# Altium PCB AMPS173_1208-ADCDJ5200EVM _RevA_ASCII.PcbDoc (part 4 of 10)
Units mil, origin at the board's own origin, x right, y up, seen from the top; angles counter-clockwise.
Board outline 10500 x 2750 mil, 14 copper layers (Top Copper, Layer 2 (GND1), Layer 3 (SIG1), Layer 4 (GND2, Layer 5 (PWR1), Layer 6 (GND3), Layer 7 (PWR/SIGNAL2), Layer 8 (PWR/SIGNAL3), Layer 9 (GND4), Layer 10 PWR2), Layer 11 (GND5), Layer 12 (SIG4), Layer 13 (GND6), Bottom Copper), stack 60.6 mil thick; 701 components, 826 nets, 3386 pads, 2128 vias.
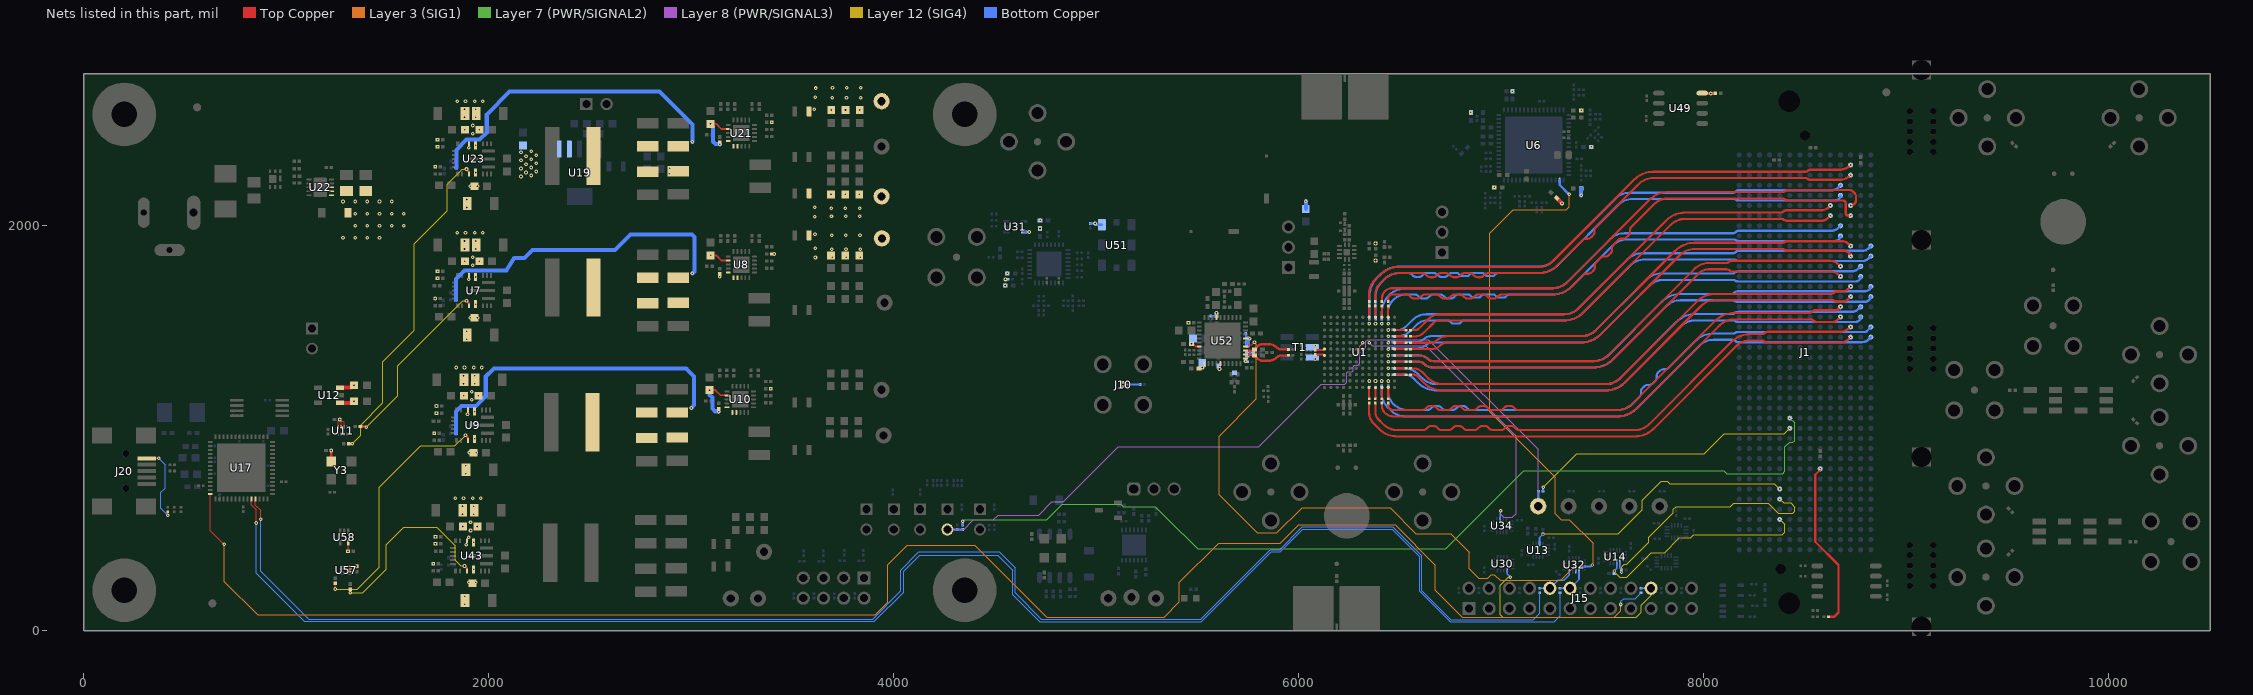
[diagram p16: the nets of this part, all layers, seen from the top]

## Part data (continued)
U17: library part CMP-0081661-1, "Future Technology Devices International Ltd FT4232H Quad High Speed USB to Multipurpose UART/MPSSE IC, VQFN-56", Manufacturer=FTDI, Supplier Part Number 1=768-1277-ND
U18: library part CMP-0081524-1, "1K Microwire Compatible Serial EEPROM, TSSOP-8", Manufacturer=Microchip, Supplier Part Number 1=93LC46B-I/ST-ND
U19: library part CMP-0036724-1, "Single Output Fast Transient Response LDO, 1.5 A,Adjustable Output, 2.1 to 20 V Input, 6-pin SOT-223 (DCQ), -40 to 125 degC, Green (RoHS & no Sb/Br)", Manufacturer="Texas Instruments"
U20: library part CMP-0005258-2, "64K I2C Smart Serial EEPROM, SOIC-8", Manufacturer=Microchip, Supplier Part Number 1=24LC65-I/SM-ND
U22: library part CMP-0074225-5, "12V, 5A, 30mO eFuse with Adjustable +/-15% Accurate Current Limit, DRC0010J (VSON-10)", Alternate Manufacturer="Texas Instruments", Alternate PartNumber=TPS259261DRCT, Operating Temperature Range="-40 to 85 C", Rating=Catalog
U30 U32 U33: library part CMP-0066255-1, "Low-Voltage 4-Bit 1-of-2 FET Multiplexer/Demultiplexer, RSV0016A (UQFN-16)", Alternate Manufacturer="Texas Instruments"
U31: library part CMP-0051325-2, "Single Power Supply, Single BUFFER GATE w/ 3-State Output (active low enable), DCK0005A, LARGE T&R", F @ Nom Voltage(Max)(Mhz)=50, Generic Part Number=SN74LV1T125, ICC @ Nom Voltage(Max)(mA)=0.01, Manufacturer="Texas Instruments", Operating Temperature Range(C)="-40 to 125", Rating=Catalog, tpd @ Nom Voltage(Max)(ns)=14.5,9.5,8.0,6.5, Voltage(Nom)(V)=1.8,2.5,3.3,5.5
U36: library part CMP-0068362-2, "Dual Micro-Power Rail-to-Rail Input CMOS Comparator with Push-Pull Output, 8-pin Narrow SOIC, Pb-Free", Manufacturer="Texas Instruments"
U41 U42: library part CMP-0051326-3, "Single Bus Buffer Gate With 3-State Outputs, DCK0005A, LARGE T&R", F @ Nom Voltage(Max)(Mhz)=150, Generic Part Number=SN74LVC1G125, ICC @ Nom Voltage(Max)(mA)=0.01, Manufacturer="Texas Instruments", Operating Temperature Range(C)="-40 to 125,-40 to 85", Rating=Catalog, tpd @ Nom Voltage(Max)(ns)=9,5.5,4.5,4, Voltage(Nom)(V)=1.8,2.5,3.3,5
U43: library part CMP-0013911-5, "5.5A, 36V Synchronous, 400kHz, Step-Down Converter, RNL0022A (VQFN-HR-22)", Alternate Manufacturer="Texas Instruments", Alternate PartNumber=LMS3655MQRNLTQ1, Operating Temprature Range="-40 to 150 C", Rating=Automotive
U49: library part CMP-0069724-2, "Automotive LVDS Dual Differential Line Receiver, D0008A (SOIC-8)", Manufacturer="Texas Instruments", Operating Temperature Range="-40 to 125 C", Rating=Automotive
U50: library part CMP-0065665-2, "3.1-GHz Differential Clock Buffer/Level Translator, RTV0032A (WQFN-32)", Alternate Manufacturer="Texas Instruments", Operating Temperature Range="-40 to 85 C"
U51: library part CMP-0075884-1, "Ultra-Low Jitter Fully Programmable Oscillator, Integrated EEPROM, +/-50ppm, SIA0008B (QFM-8)", Alternate Manufacturer="Texas Instruments", Alternate PartNumber=LMK61E2-SIAT
U52: library part CMP-0013786-6, "15 GHz Wideband PLLatinum(TM)RF Synthesizer with Phase Synchronization and JESD204B support, RHA0040H (VQFN-40)", Alternate Manufacturer="Texas Instruments", Alternate PartNumber=LMX2594RHAT
U58: library part CMP-0051690-3, "Single Inverter, DRL0005A, LARGE T&R", Alternate Manufacturer="Texas Instruments", F @ Nom Voltage(Max)(Mhz)=150, Generic Part Number=SN74LVC1G04, ICC @ Nom Voltage(Max)(mA)=0.01, Operating Temperature Range(C)="-40 to 125,-40 to 85", Rating=Catalog, tpd @ Nom Voltage(Max)(ns)=7.5,5.2,4.2,3.7, Voltage(Nom)(V)=1.8,2.5,3.3,5
U59: library part CMP-0051421-4, "Low-Power Single 2-Input Positive-AND Gate, DRY0006A (USON-6)", F @ Nom Voltage(Max)(Mhz)=100, Generic Part Number=SN74AUP1G08, ICC @ Nom Voltage(Max)(mA)=0.0009, Manufacturer="Texas Instruments", Operating Temperature Range="-40 to 85 C", Operating Temperature Range(C)="-40 to 85", Rating=Catalog, tpd @ Nom Voltage(Max)(ns)=32.8,20.9,14.2,11,7.6,6.2, Voltage(Nom)(V)=0.8,1.2,1.5,1.8,2.5,3.3
Y1: library part CMP-0004616-3, "Crystal, 12 MHz, 18 pF, SMD", Frequency_Fixed=12MHz, Frequency Stability=+/-30ppm, Manufacturer="Abracon Corporation", Supplier Part Number 1=535-10634-1-ND
Y3: library part CMP-0006092-3, "OSC, 1 MHz, 3.3V, SMD", Frequency_Fixed=1MHz, Frequency Stability=+/-25ppm, Manufacturer="Fox Electronics", Supplier Part Number 1=631-1317-1-ND
ZZ1: library part CMP-0003616-3
ZZ2: library part CMP-0077236-1
ZZ3: library part CMP-0077237-1
ZZ4: library part CMP-0077238-1

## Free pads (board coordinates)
  round 10 hole 106 unplated: 1(8421,135) 1(8421,2615)
  round 31 hole 31 unplated: 1(9017.5,222.25) 1(9017.5,272.25) 1(9017.5,322.25) 1(9017.5,372.25) 1(9017.5,422.25) 1(9017.5,1293.75) 1(9017.5,1343.75) 1(9017.5,1393.75) 1(9017.5,1443.75) 1(9017.5,1493.75) 1(9017.5,2365.25) 1(9017.5,2415.25) 1(9017.5,2465.25) 1(9017.5,2515.25) 1(9017.5,2565.25) 1(9132.5,222.25) 1(9132.5,272.25) 1(9132.5,322.25) 1(9132.5,372.25) 1(9132.5,422.25) 1(9132.5,1293.75) 1(9132.5,1343.75) 1(9132.5,1393.75) 1(9132.5,1443.75) 1(9132.5,1493.75) 1(9132.5,2365.25) 1(9132.5,2415.25) 1(9132.5,2465.25) 1(9132.5,2515.25) 1(9132.5,2565.25)
  rect 93x93 hole 100 slot 469 at 90 deg unplated: 1(9075,19.75) 1(9075,2768.75)
  rect 93x93 hole 100 slot 933.5 at 90 deg unplated: 1(9075,858) 1(9075,1929.5)

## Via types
v1: diameter 18, hole 8, Top Copper to Bottom Copper, tented both sides, 1234 vias
v2: diameter 18, hole 8, Top Copper to Bottom Copper, tented top, 219 vias
v3: diameter 16, hole 8, Top Copper to Bottom Copper, tented both sides, 138 vias
v4: diameter 19.68, hole 7.87, Top Copper to Bottom Copper, 103 vias
v5: diameter 20, hole 10, Top Copper to Bottom Copper, tented top, 96 vias
v6: diameter 20, hole 10, Top Copper to Bottom Copper, tented both sides, 71 vias
v7: diameter 15.75/18/18/18/16/18/18/18/18/16/18/18/18/18 (per signal layer), hole 8, Top Copper to Bottom Copper, 50 vias
v8: diameter 20, hole 10, Top Copper to Bottom Copper, 40 vias
v9: diameter 15.75, hole 7.87, Top Copper to Bottom Copper, 28 vias
v10: diameter 21.81, hole 10, Top Copper to Bottom Copper, 26 vias
v11: diameter 15.75/16/16/16/16/16/16/16/16/16/16/16/16/18 (per signal layer), hole 8, Top Copper to Bottom Copper, 26 vias
v12: diameter 18, hole 8, Top Copper to Bottom Copper, tented bottom, 18 vias
v13: diameter 25.75, hole 15.75, Top Copper to Bottom Copper, 16 vias
v14: diameter 15.75/16/16/16/16/16/16/18/16/16/16/16/16/18 (per signal layer), hole 8, Top Copper to Bottom Copper, 15 vias
v15: diameter 30, hole 15, Top Copper to Bottom Copper, tented both sides, 12 vias
v16: diameter 15.75/16/16/16/18/16/16/16/16/16/16/16/16/18 (per signal layer), hole 8, Top Copper to Bottom Copper, 11 vias
v17: diameter 15.75/16/16/16/16/16/16/16/16/18/16/16/16/18 (per signal layer), hole 8, Top Copper to Bottom Copper, 7 vias
v18: diameter 15.75/16/16/16/16/16/16/18/16/18/16/16/16/18 (per signal layer), hole 8, Top Copper to Bottom Copper, 5 vias
v19: diameter 119.29, hole 77.95, Top Copper to Bottom Copper, 4 vias
v20: diameter 18, hole 8, Top Copper to Bottom Copper, 4 vias
v21: diameter 15.75/16/16/16/18/16/16/18/16/16/16/16/16/18 (per signal layer), hole 8, Top Copper to Bottom Copper, 2 vias
v22: diameter 15.75/16/16/16/16/16/18/16/16/16/16/16/16/18 (per signal layer), hole 8, Top Copper to Bottom Copper, 2 vias
v23: diameter 15.75/16/16/16/16/16/18/18/16/16/16/16/16/18 (per signal layer), hole 8, Top Copper to Bottom Copper, 1 vias

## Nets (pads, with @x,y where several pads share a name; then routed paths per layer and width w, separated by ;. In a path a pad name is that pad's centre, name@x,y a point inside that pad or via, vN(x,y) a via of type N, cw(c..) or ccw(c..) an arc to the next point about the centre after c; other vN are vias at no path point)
3.3V-LMX: C307.1 C308.1 C309.1 C326.1 C327.2 C328.2 C329.2 C330.2 C331.1 C332.1 C334.1 C335.1 FB7.2 L34.1 R262.2 TP21.1 U52.7 U52.11 U52.15 U52.26 U52.37 | length 229.7
  Top Copper w6: v1(5524.21,1299.79) 5534.45,1310.04 U52.11@5534.45,1319.2 ; v1(5608.21,1292.79) 5613.19,1297.78 U52.15@5613.19,1319.2 ; U52.26@5737.21,1443.22 5738.43,1442 v1(5758,1442)
  Top Copper w8: v1(5470.27,1416.79) 5478.21,1416.79 5491.15,1403.85 U52.7@5508.86,1403.85 ; U52.37@5593.5,1547.55 v1(5593.5,1570.1) cw(c5595.9,1570.1) v1@5594.21,1571.79
  Bottom Copper w8: C329.2@5566,1555.02 5592.75,1555.02 C335.1@5594.21,1556.48 ; C330.2@5738.02,1469 5738.02,1451.66 C326.1@5745.89,1443.79
  Bottom Copper w20: L34.1@5745.21,1413.42 5745.89,1414.1 C326.1@5745.89,1443.79
  other v1: 5455.21,1521.79 3610,2045 3692.09,2046.5 3762.09,2046.5 3832.09,2046.5 3691.09,2086 3761.09,2086 3831.09,2086 3609,2091 3690,2155 3760,2155 3830,2155
3.3V-LMXRF: C325.1 L33.2 L34.2 L35.2 U52.21 | length 14
  Top Copper w8: v1(5737.21,1330.79) U52.21@5737.21,1344.79
3p3VAMP: C109.1 C110.1 C111.1 FB3.2 R3.2 R4.2 R179.2 TP16.1 | length 37
  Bottom Copper w20: R179.2@6035,2083.97 v7(6035,2121)
  other v1: 3613.09,1843.02 3695.17,1844.52 3765.17,1844.52 3835.17,1844.52 3694.17,1884.02 3764.17,1884.02 3834.17,1884.02 3612.09,1889.02 3693.09,1953.02 3763.09,1953.02 3833.09,1953.02 3611,1958.02
  other v5: 6379.5,1827.94 6379.5,1912.98
3P3VAUX-FMC: J1.D32 R215.1 | length 825.3
  Top Copper w11.5: v2(8575,800) 8575,795 8550,770 8550,440 8665,325 8665,90 8645,70 R215.1@8616.02,70
5V-USB: J20.1 R162.1 | length 395.6
  Top Copper w5: v1(414,570) R162.1@414,587.98
  Top Copper w8: J20.1@310.47,851.8 v1(369.8,851.8)
  Bottom Copper w5: v1(369.8,851.8) 402,819.59 402,705 380,683 380,604 v1(414,570)
+1.4V: C8.1 C9.1 C135.1 C143.1 C243.1 L1.2 R96.2 U8.15 U8.16 U8.17 | length 1568.8
  Bottom Copper w20: C143.1@1837.99,1635 R96.2@1837.99,1670 1837.99,1737.99 1879,1779 2087.38,1779 2107,1810.71 2125.98,1841.39 2175.39,1841.39 2215,1881 2624,1881 2700,1957 3003,1957 3015,1945 3015,1775 v1(3005,1765)
+2.2V: C10.1 C11.1 C12.1 C190.1 C194.1 L2.2 R115.2 U10.15 U10.16 U10.17 | length 1605.6
  Bottom Copper w20: R115.2@1837.99,975 C194.1@1837.99,1010 1837.99,1082.99 1866,1111 1936,1111 1985,1160 1985,1255 2025,1295 2975,1295 3014.25,1255.75 3014.25,1114.25 v1(3000,1100)
+3.3VA: C142.1 C195.1 C204.2 C206.1 C207.2 C359.2 C360.2 R92.1 R93.2 R94.1 R95.2 R99.2 R113.1 R114.2 R116.1 R117.2 R119.2 R130.1 R131.2 R134.2 R136.2 R228.2 R230.2 R231.2 U8.12 U10.12 U11.6 U11.7 U11.8 U12.1 U57.6 U57.7 U57.8 U58.5 Y3.4 | length 701.1
  Top Copper w6: U11.8@1257.46,1006.58 C207.2@1257.46,1036.46 ; U11.7@1271.24,1006.58 1271.24,1035.76 1280.24,1035.76 1285.02,1030.98 U11.6@1285.02,1006.58 ; v1(1305.02,393) 1305.69,393.67 U58.5@1305.69,433.87
  Top Copper w7: U57.6@1313.72,291.11 U57.7@1313.72,304.89 U57.8@1313.72,318.67
  Top Copper w8: U57.8@1313.72,318.67 v1(1348.32,318.67)
  Top Copper w9: v1(3090,1188.5) 3118.5,1188.5 3144.32,1162.68 U10.12@3177.04,1162.68 ; C142.1@3095,1853.5 v1(3097,1853.5) 3123.5,1853.5 3149.32,1827.68 U8.12@3182.04,1827.68 ; v1(3135,1082) R116.1@3135,1097.01 ; v1(3140,1748) R94.1@3140,1762.01 ; R92.1@3397.99,1860.75 v1(3410.25,1860.75)
  Top Copper w12: v1(1221.99,890) 1221.99,836.29 Y3.4@1222.13,836.16
  Top Copper w20: U12.1@1265.13,1125.6 1327.1,1125.6 v1(1334.5,1133) ; v1(1348.32,318.67) C359.2@1349,317.99
  Bottom Copper w20: v1(3090,1188.5) 3090,1165 3104,1151 3104,1097 3117,1084 3133,1084 v1(3135,1082)
  other v1: 1725,330.75 1737.01,430 1737.01,465 1730,975.75 1263.99,1043 1742.01,1075 1742.01,1110 3392.99,1195.75 1735,1640.75 1747.01,1740 1747.01,1775 1735,2290.75 1747.01,2390 1747.01,2425 3397.99,2510.75
+3.3VCLK: C51.1 C96.1 C224.1 C225.1 C226.1 C315.1 C316.1 C323.1 FB5.2 L3.1 L4.1 L5.1 L6.1 L7.1 L11.1 L12.1 L31.2 L32.1 TP10.1 U31.5 U49.8 U51.6 | length 225
  Top Copper w11.5: L5.1@7273.92,2133.92 L5.1@7273.92,2136.08 ; v1(7299.69,2110.32) v1@7300,2110
  Top Copper w15.5: U49.8@7992.28,2655 ccw(c7997.13,2659.85) 7997.13,2652.99 v1(8035,2652.99) 8055,2652.99 C51.1@8057.01,2655
  Top Copper w20: L5.1@7273.92,2136.08 v1(7299.69,2110.32)
  Bottom Copper w11.5: U31.5@4644.29,1969.41 v1(4669.41,1969.41) ; C323.1@4970,2011.02 v1(4993.98,2011.02) 5000,2005 U51.6@5027.17,2005 ; v1(7394.69,2150.32) v1@7395,2150
  Bottom Copper w20: v1(7394.69,2150.32) L4.1@7394.69,2185
  other v1: 4550.31,1705 4551.38,1735 4560.31,1765 4722.09,1986.77 4722.4,2027.09 6965.31,2190 7444.69,2390 6850,2559.68 7394.69,2570 3691.46,2571.5 3761.46,2571.5 3831.46,2571.5 3607.91,2575 3696.54,2631.5 3766.54,2631.5 3836.54,2631.5 3613,2635 7055,2664.69 3615,2680 3697.09,2681.5 3767.09,2681.5 3837.09,2681.5
+3.6V: C215.1 C216.1 C217.1 C218.1 C222.1 C223.1 L17.2 R132.2 R133.2 U21.12 U21.15 U21.16 U21.17 | length 1808.1
  Top Copper w9: v1(3095,2503.5) 3123.5,2503.5 3149.32,2477.68 U21.12@3182.04,2477.68
  Bottom Copper w20: C222.1@1840,2285 R133.2@1840,2320 1840,2375 1890,2425 1954,2425 1990,2461 1990,2550 2102,2662 2842,2662 3005,2499 v1(3005,2415) ; v1(3095,2503.5) 3107,2491.5 3107,2415 3119,2403 3140,2403 v1(3141,2402)
  other v1: 2892,2256.95 2893,2283.95
+7V: C68.1 C69.1 C70.1 C71.1 C72.1 C100.1 C112.1 C128.1 C130.1 C131.1 C132.1 C133.1 C134.1 C184.1 C185.1 C186.1 C187.1 C188.1 C189.1 C205.1 C209.1 C210.1 C211.1 C212.1 C213.1 C214.1 C236.1 C237.1 D6.1 U7.4 U7.14 U7.15 U9.4 U9.14 U9.15 U12.3 U19.1 U19.2 U22.6 U22.7 U22.8 U23.4 U23.14 U23.15 U43.4 U43.14 U43.15 | length 74.6
  Top Copper w20: U12.3@1265.13,1200.4 1321.91,1200.4 v1(1334.5,1213)
  other v1: 1881.1,130 1881.1,170 1901,239 1935,239 1889,425 1901,462 1910,495 1871.5,515 1943.5,515 1910,535 1870,575 1926.1,575 1870,615 1926.1,615 1835,655 1875,655 1920,655 1960,655 1886.1,775 1886.1,815 1904,880 1938,880 1895,1070 1915,1140 1876.5,1160 1948.5,1160 1915,1180 1875,1220 1931.1,1220 1875,1260 1931.1,1260 1840,1300 1880,1300 1925,1300 1965,1300 1891.1,1440 1891.1,1480 1909,1545 1944,1545 1901,1736 1920,1805 1881.5,1825 1953.5,1825 1920,1845 1880,1885 1936.1,1885 1880,1925 1936.1,1925 1280,1940 1340,1940 1400,1940 1460,1940 1845,1965 1885,1965 1930,1965 1970,1965 1340,2000 1400,2000 1460,2000 1520,2000 1580,2000 1340,2060 1400,2060 1460,2060 1520,2060 1580,2060 1891.1,2090 1280,2120 1340,2120 1400,2120 1460,2120 1520,2120 1891.1,2130 1909,2195 1944,2195 2159.01,2243.02 2209.01,2248.02 2184.01,2263.02 2234.01,2268.02 2159.01,2283.02 2209.01,2288.02 2184.01,2303.02 2234.01,2308.02 2159.01,2323.02 2209.01,2328.02 2184.01,2343.02 2234.01,2348.02 2159.01,2363.02 2209.01,2368.02 1901,2385 1920,2455 1881.5,2475 1953.5,2475 1920,2495 1880,2535 1936.1,2535 1880,2575 1936.1,2575 1845,2615 1885,2615 1930,2615 1970,2615
  other v9: 1924.84,303.07 1924.84,436.93 1929.84,948.07 1929.84,1081.93 1934.84,1613.07 1934.84,1746.93 1934.84,2263.07 1934.84,2396.93
CALSTAT_ADC: R219.2 TP15.1 U1.F7 | length 1482.6
  Layer 8 (PWR/SIGNAL3) w3.3: v14@6316.76,1390.75 6321.76,1390.75 6331.4,1400.39 6331.4,1428.53 6340.87,1438 6640,1438 7182.5,895.5 TP15.1@7182.5,615
  Bottom Copper w8: TP15.1@7182.5,615 7183.98,616.48 R219.2@7183.98,690
  other v14: 6315.75,1390.75
CALSTAT_FMC: J1.G28 R219.1 | length 1357.9
  Layer 12 (SIG4) w4: v3(7207,709) 7373,875 8002.05,875 8100,972.95 8397.95,972.95 v1(8425,1000)
  Bottom Copper w8: R219.1@7206.02,690 7206.02,708.02 v3(7207,709)
CALTRIG_ADC: J18.2 R60.1 R69.2 U1.E7 | length 2597.2
  Layer 8 (PWR/SIGNAL3) w3.3: J18.2@4266.01,500 4345.01,500 4392.01,547 4492,547 4516,571 4715.01,571 4781,637 4838,637 5109,908 5802,908 6111.62,1217.62 6227.74,1217.62 6237,1226.88 6237,1274 6243,1280 6264,1280 6268,1284 6268,1305 6275,1312 6291,1312 6300.1,1321.1 6300.1,1404.09 6316.76,1420.75 v14@6316.76,1422.24
  Bottom Copper w11.5: J18.2@4265,500 R69.2@4313,500 R60.1@4340,500
  other v14: 6315.75,1422.24
CALTRIG_FMC: J1.G27 R60.2 | length 4677.9
  Layer 7 (PWR/SIGNAL2) w4: v1(4340,540) 4348,548 4756.05,548 4832.97,624.92 5121.34,624.92 5133.31,612.95 5291.05,612.95 5424.32,479.68 5426.27,479.68 5501.78,404.18 6168.39,404.18 6169.35,405.14 6204.65,405.14 6205.61,404.18 6725.5,404.18 7111.27,789.95 8099,789.95 8113,775.95 8390,775.95 8401,786.95 8401,907.95 8424,930.95 8440,930.95 8448,938.95 8448,1027 v1(8425,1050)
  Bottom Copper w11.5: R60.2@4340,522.05 v1(4340,540)
CLK0-500k: R127.2 U7.3 | length 900.4
  Top Copper w9.8: v1(1890,1630) 1902.36,1617.64 U7.3@1902.36,1605.2
  Top Copper w11.5: R127.2@1366.12,1008.87 1390.13,1008.87 v1(1394,1005)
  Layer 12 (SIG4) w3.3: v1(1394,1005) 1550,1161 1550,1308 1872,1630 v1(1890,1630)
CLK1-500k: R129.2 U9.3 | length 1247.7
  Top Copper w4: v1(1241,206) R129.2@1241,234.01
  Top Copper w9.8: v1(1885,965) 1897.36,952.64 U9.3@1897.36,940.2
  Layer 12 (SIG4) w4: v1(1241,206) 1351,206 1459,314 1459,709 1663,913 1833,913 v1(1885,965)
CLK2-500k: R128.2 U23.3 | length 1632.5
  Top Copper w9.8: v1(1890,2280) 1902.36,2267.64 U23.3@1902.36,2255.2
  Layer 12 (SIG4) w3.3: v1(1325.53,923) 1367,964.47 1367,1016 1476,1125 1476,1328 1632,1484 1632,1912 1795,2075 1795,2205 1870,2280 v1(1890,2280)
CLK3-500k: R233.2 U43.3 | length 940.9
  Top Copper w9.8: v1(1880,320) 1892.36,307.64 U43.3@1892.36,295.2
  Top Copper w11.5: v1(1316,187) R233.2@1316,205.01
  Layer 12 (SIG4) w3.3: v1(1316,187) 1377,187 1493,303 1493,425 1580,512 1744,512 1835,421 1835,347 1862,320 v1(1880,320)
CLK_ADC_LMX_N: C45.2 R253.1 U52.22 | length 230.7
  Top Copper w10: U52.22@5737.21,1364.48 5770.34,1364.48 cw(c5770.34,1348.67) R253.1@5781.52,1359.85
  Top Copper w11.5: R253.1@5781.34,1359.85 5798.73,1342.46 ccw(c5820,1363.73) 5820,1333.64 5853.79,1333.64 ccw(c5853.79,1384.86) 5890,1348.64 cw(c5916.56,1322.09) 5916.56,1359.64 C45.2@5949.98,1359.64
CLK_ADC_LMX_P: C46.2 R252.1 U52.23 | length 230.7
  Top Copper w10: U52.23@5737.21,1384.16 5770.34,1384.16 ccw(c5770.34,1399.97) R252.1@5781.52,1388.79
  Top Copper w11.5: R252.1@5781.34,1388.79 5798.73,1406.19 cw(c5820,1384.92) 5820,1415 5853.79,1415 cw(c5853.79,1363.79) 5890,1400 ccw(c5916.56,1426.56) 5916.56,1389 C46.2@5949.98,1389
CLK_ADC_N: C2.1 R171.2 U1.G1 | length 48
  Top Copper w10.5: C2.1@6081.05,1364 6122.02,1364 U1.G1@6126.77,1359.25 U1.G1@6126.54,1359.02
CLK_ADC_P: C3.1 R174.2 U1.F1 | length 47.7
  Top Copper w10: R174.2@6081.05,1386 6122.02,1386 U1.F1@6126.77,1390.75
CLK_SMA: C285.2 J10.1 | length 85
  Bottom Copper w10: v20(5132,1216) C285.2@5216.95,1216
CLK_TX_N: C2.2 T1.4
  other v3: 6081.05,1341.95
CLK_TX_P: C3.2 T1.5
  other v3: 6081.05,1408.05
CSb_ADC: U1.E8 U34.10 | length 1450.2
  Layer 8 (PWR/SIGNAL3) w3.3: v14@6348.25,1422.24 6363.9,1406.59 6627.41,1406.59 7073,961 7073,577.99 7055.01,560 7013.01,560 6998.01,575 v3@6998.01,593
  Bottom Copper w8: U34.10@6994.13,549.5 6994.13,590.13 v3(6997,593)
  other v14: 6347.24,1422.24
CSb_ADC_FMC: J1.H34 R75.2 U13.3 | length 1374.8
  Layer 12 (SIG4) w4: v3(7205.98,477.36) 7208.57,479.95 7578,479.95 7696,597.95 7696,644.68 7789.27,737.95 7819,737.95 7831,725.95 8349.05,725.95 v1(8375,700)
  Bottom Copper w8: U13.3@7188.62,429.84 7188.62,460.01 v3(7205.98,477.36)
CSb_ADC_HDR: J15.20 R72.2 U30.9 | length 1152
  Layer 12 (SIG4) w3.3: v1(7045,265) 7035,265 6995,225 6995,80 7008,67 7666.1,67 7690,90.9 7690,125 7740,175 J15.20@7740,210
  Bottom Copper w8: U30.9@7028.62,298.5 7028.62,281.38 v1(7045,265) ; R72.2@7690,210 J15.20@7740,210
CSb_ADC_USB: R72.1 U17.14 | length 8509.7
  Top Copper w4: U17.14@624.82,676.55 624.82,494.18 692,427 v1(694,427)
  Layer 3 (SIG1) w3.3: v1(694,427) 694,243 859,78 3907.97,78 3970.95,140.98 3970.95,325.98 4067.02,422.05 4400.95,422.05 4756,67 5335.2,67 5410.65,142.45 5410.65,238.42 5603.93,431.7 5909.17,431.7 5999.82,522.35 6475.97,522.35 6674.4,323.92 6674.4,199.4 6806.8,67 7559,67 7590,98 v1(7590,130)
  Bottom Copper w5: v1(7590,130) 7590,145 7604,159 7661.05,159 R72.1@7690,187.95
CSb_LMK: U6.18 U32.7 | length 2518.1
  Layer 3 (SIG1) w3.3: v1@7335,2154.5 v1(7335,2155) ; v1@7336.01,2155 7335.5,2154.5 7335.5,2093.8 7321.5,2079.8 7058.8,2079.8 6943,1964 6943,1082 7266.01,758.99 7266.01,577 7295.01,548 7336,548 7453.01,430.99 7453.01,328 v3@7450.01,325
  Bottom Copper w8: U32.7@7407.24,317.13 7441.13,317.13 v3(7449,325)
  Bottom Copper w11.5: U6.18@7288.27,2225 7288.27,2201.73 v1(7335,2155)
CSb_LMK_FMC: J1.H35 R77.2 U14.1 | length 1222.2
  Layer 12 (SIG4) w4: v3(7593.98,288.02) 7593.98,314.93 7607,327.95 7619,327.95 7729,437.95 7729,461.63 7850,582.63 7850,599.03 7862.92,611.95 8131,611.95 8148,628.95 8319,628.95 8367.17,580.78 8438.83,580.78 8449,590.95 8449,610.95 8429,630.95 8394.05,630.95 v1(8375,650)
  Bottom Copper w8: U14.1@7585.75,336.97 7585.75,308.23 R77.2@7593.98,300 v3(7593.98,288.02)
CSb_LMK_HDR: J15.12 R88.2 U32.9 | length 151.6
  Bottom Copper w8: R88.2@7290,210 J15.12@7340,210 7383.62,253.62 U32.9@7383.62,293.5
CSb_LMK_USB: R88.1 U17.24 | length 7924.3
  Top Copper w5: U17.24@827.57,650.96 827.57,622.28 852,597.86 v1(852,532)
  Bottom Copper w5: v1(852,532) 852,283 1089,46 3904,46 4048,190 4048,294 4128,374 4514,374 4588,300 4588,178 4721,45 5518.14,45 5864.14,391 5909.14,391 6020.57,502.43 6461.22,502.43 6597.79,365.86 6597.79,194.1 6746.89,45 7261,45 7290,74 R88.1@7290,187.95
CSb_LMX: U32.10 U52.24 | length 3039.5
  Top Copper w4: U52.24@5737.21,1403.85 5744.26,1403.85 5752.21,1411.79 5768.21,1411.79 v1(5781.21,1424.79)
  Layer 3 (SIG1) w3.3: v1(5781.21,1424.79) 5791,1415 5791,1145 5606,960 5606,672 5795,483 5892,483 6016,607 6451,607 6578,480 6750,480 6842,388 6842,307 6889,260 6932.1,260 6949.26,277.16 6966.48,277.16 6994.29,249.35 7294.7,249.35 7363.5,318.15 v3@7363.5,318.5
  Bottom Copper w8: v3(7363,319) 7367.87,314.13 U32.10@7367.87,293.5
CSb_LMX_FMC: J1.H37 R78.2 U14.2 | length 1068
  Layer 12 (SIG4) w4: v3(7557.99,295) 7557.99,291.96 7586,263.95 7619,263.95 7741,385.95 7807,385.95 7880.05,459 7936.21,459 7951.17,473.95 8388,473.95 8400,485.95 8400,525 v1(8375,550)
  Bottom Copper w8: v3(7557.99,295) 7570,307.01 U14.2@7570,335
CSb_LMX_HDR: J15.10 R106.2 U32.12 | length 191
  Bottom Copper w8: R106.2@7190,210 J15.10@7240,210 7280,250 7310,250 7336.38,276.38 U32.12@7336.38,293.5
CSb_LMX_USB: R106.1 U17.25 | length 7781.6
  Top Copper w5: U17.25@847.26,650.96 847.26,620.74 874,594 v1(874,550)
  Bottom Copper w5: v1(874,550) 874,295 1111,58 3895,58 4035,198 4035,300 4124,389 4521,389 4600,310 4600,187 4729,58 5517,58 5860,401 5905,401 6018,514 6463.79,514 6607.79,370 6607.79,198.24 6751.03,55 7159,55 7190,86 R106.1@7190,187.95
DA0_ADC_N: C14.2 U1.F12 | length 55.9
  Top Copper w10.5: U1.F12@6472.98,1391 6473.23,1391.24 C14.2@6528.73,1391.24
DA0_ADC_P: C13.2 U1.E12 | length 55.9
  Top Copper w10.5: U1.E12@6472.98,1422.49 U1.E12@6473.23,1422.24 6516.38,1422.24 C13.2@6528.73,1422.26
DA0_FMC_N: C14.1 J1.A11 | length 2379.2
  Top Copper w10.5: C14.1@6551.02,1391.01 6656.71,1391.01 ccw(c6656.71,1449.29) 6697.92,1408.08 cw(c6736.36,1369.64) 6736.36,1424 7396.58,1424 ccw(c7396.58,1555) 7489.21,1462.37 7882.55,1855.71 cw(c7953.26,1785) 7953.26,1885 8388,1885 cw(c8388,1867.1) 8400.66,1879.76
  Top Copper w11.5: 8400.66,1879.76 ccw(c8409.73,1888.83) 8409.73,1876 8689,1876 8691.44,1876 cw(c8691.44,1838.44) 8718,1865 8719.34,1863.66 cw(c8705.69,1850) v2(8725,1850)
DA0_FMC_P: C13.1 J1.A10 | length 2378.9
  Top Copper w10.5: C13.1@6551.02,1422.01 6656.71,1422.01 ccw(c6656.71,1449.29) 6676,1430 cw(c6736.36,1369.64) 6736.36,1455 7396.58,1455 ccw(c7396.58,1555) 7467.29,1484.29 7860.63,1877.63 cw(c7953.26,1785) 7861.64,1878.63 cw(c7953.26,1785) 7953.26,1916 8388,1916 ccw(c8388,1935.31) 8401.59,1921.6
  Top Copper w11.5: 8397.56,1918.53 cw(c8410.76,1905.33) 8401.59,1921.6 cw(c8410.76,1905.33) 8410.76,1924 8683.25,1924 cw(c8683.25,1881.14) 8713.55,1911.45 v2(8725,1900)
DA1_ADC_N: C16.2 U1.D12 | length 55.9
  Top Copper w10.5: U1.D12@6472.98,1453.99 6473.23,1454.24 C16.2@6528.73,1454.24
DA1_ADC_P: C15.2 U1.C12 | length 55.9
  Top Copper w10.5: U1.C12@6472.98,1485.48 U1.C12@6473.23,1485.24 6516.38,1485.24 C15.2@6528.73,1485.25
DA1_FMC_N: C16.1 J1.C7 | length 2310.9
  Top Copper w10.5: C16.1@6551.02,1454 6574,1454 ccw(c6574,1513.97) 6616.41,1471.56 6664.92,1520.08 cw(c6693.7,1491.3) 6693.7,1532 7310.58,1532 ccw(c7310.58,1663) 7403.21,1570.37 7837.55,2004.71 cw(c7908.26,1934) 7908.26,2034 8388.68,2034 cw(c8388.68,2029.18) 8392.08,2032.59
  Top Copper w11.5: 8392.08,2032.59 ccw(c8410.4,2050.91) 8401.19,2026.69 ccw(c8410.4,2050.91) 8410.4,2025 8582.25,2025 ccw(c8582.25,2067.86) 8612.55,2037.55 v2(8625,2050)
DA1_FMC_P: C15.1 J1.C6 | length 2310.5
  Top Copper w10.5: C15.1@6551.02,1485 6574,1485 ccw(c6574,1513.97) 6594.49,1493.49 6643,1542 cw(c6693.7,1491.3) 6693.7,1563 7310.58,1563 ccw(c7310.58,1663) 7381.29,1592.29 7815.63,2026.63 cw(c7908.26,1934) 7908.26,2065 8379.56,2065 ccw(c8379.56,2083.59) 8392.7,2070.44
  Top Copper w11.5: 8392.7,2070.44 cw(c8406.11,2057.03) 8406.11,2076 8578.76,2076 ccw(c8578.76,2129.69) 8616.71,2091.71 v2(8625,2100)
DA2_ADC_N: C18.2 U1.A11 | length 55.9
  Top Copper w10.5: C18.2@6441.24,1603.73 6441.24,1548.23 U1.A11@6441.48,1547.98
DA2_ADC_P: C17.2 U1.A10 | length 55.9
  Top Copper w10.5: U1.A10@6409.99,1547.98 U1.A10@6410.24,1548.23 6410.24,1591.38 ; 6410.22,1591.39 C17.2@6410.22,1603.73
DA2_FMC_N: C18.1 J1.A7 | length 2649.7
  Top Copper w10.5: C18.1@6441.47,1626.02 6441.47,1639.24 cw(c6463.76,1639.24) 6448,1655 cw(c6461.83,1641.17) 6461.83,1660.73 6533,1660.73 cw(c6533,1641.42) 6533.06,1660.73 cw(c6533,1641.42) 6546.66,1655.07 6553,1648.73 ; 6553.01,1648.72 ccw(c6572.32,1668.05) 6572.32,1640.73 6584,1640.73 ccw(c6584,1662.46) 6599.36,1647.09 6605.93,1653.66 cw(c6623,1636.59) 6623,1660.73 6680.06,1660.73 cw(c6680,1641.42) 6693.66,1655.07 6700,1648.73 ; 6700.01,1648.72 ccw(c6719.32,1668.05) 6719.32,1640.73 6731,1640.73 ccw(c6731,1662.46) 6746.36,1647.09 6752.93,1653.66 cw(c6770,1636.59) 6770,1660.73 6796,1660.73 cw(c6796,1641.42) 6809.66,1655.07 6816,1648.73 ; 6816.01,1648.72 ccw(c6835.32,1668.05) 6835.32,1640.73 6847,1640.73 ccw(c6847,1662.46) 6862.36,1647.09 6868.93,1653.66 cw(c6886,1636.59) 6886,1660.73 6913,1660.73 cw(c6913,1641.42) 6926.66,1655.07 6933,1648.73 ; 6933.01,1648.72 ccw(c6952.32,1668.05) 6952.32,1640.73 6964,1640.73 ccw(c6964,1662.46) 6979.36,1647.09 6985.93,1653.66 cw(c7003,1636.59) 7003,1660.73 7254.31,1660.73 ccw(c7254.31,1791.73) 7346.94,1699.1 7405.2,1757.36 cw(c7418.86,1743.7) 7418.86,1763.02 7427.83,1763.02 ccw(c7427.83,1790.35) 7447.15,1771.02 7455.41,1779.28 ccw(c7440.04,1794.64) 7461.77,1794.64 7461.77,1803.93 cw(c7485.91,1803.93) 7468.81,1820.97 7490.2,1842.36 cw(c7503.86,1828.7) 7503.86,1848.02 7512.83,1848.02 ccw(c7512.83,1875.35) 7532.15,1856.02 7540.41,1864.28 ccw(c7525.04,1879.64) 7546.77,1879.64 7546.77,1888.93 cw(c7570.91,1888.93) 7553.81,1905.97 7578.2,1930.36 cw(c7591.86,1916.7) 7591.86,1936.02 7600.83,1936.02 ccw(c7600.83,1963.35) 7620.15,1944.02 7628.41,1952.28 ccw(c7613.04,1967.64) 7634.77,1967.64 7634.77,1976.93 cw(c7658.91,1976.93) 7641.81,1993.97 7754.08,2106.24 cw(c7824.79,2035.53) 7824.79,2135.53 8384,2135.53 cw(c8384,2102.72) 8398.22,2132.29
  Top Copper w11.5: 8398.22,2132.29 ccw(c8415.67,2149.74) 8406.06,2127.01 ccw(c8415.67,2149.74) 8415.67,2125.06 8439,2125.06 8686.08,2125.06 cw(c8686.08,2110.38) 8696.46,2120.76 cw(c8686.05,2110.35) 8700.77,2110.35 8700.77,2063.4 ccw(c8714.17,2063.4) 8714.17,2050 v2(8725,2050)
DA2_FMC_P: C17.1 J1.A6 | length 2650.2
  Top Copper w10.5: C17.1@6410.47,1626.02 6410.47,1639.24 cw(c6463.76,1639.24) 6426.08,1676.92 cw(c6461.83,1641.17) 6461.83,1691.73 7254.31,1691.73 ccw(c7254.31,1791.73) 7325.02,1721.02 7732.16,2128.16 cw(c7824.79,2035.53) 7824.79,2166.53 8387,2166.53 ccw(c8387,2190.67) 8398.91,2169.67 cw(c8416.6,2151.99) 8404.15,2173.68
  Top Copper w11.5: 8404.15,2173.68 cw(c8416.6,2151.99) 8416.6,2177 8713.88,2177 cw(c8713.88,2137.88) 8751.31,2149.25 8751.31,2126.31 cw(c8725,2126.31) v2(8725,2100)
DA3_ADC_N: C20.2 U1.A9 | length 55.9
  Top Copper w10.5: C20.2@6378.24,1603.73 6378.24,1548.23 U1.A9@6378.49,1547.98
DA3_ADC_P: C19.2 U1.A8 | length 55.9
  Top Copper w10.5: U1.A8@6347,1547.98 U1.A8@6347.24,1548.23 6347.24,1591.38 C19.2@6347.23,1603.73
DA3_FMC_N: C20.1 J1.A3 | length 2675.2
  Top Copper w10.5: C20.1@6378.48,1629.9 6378.48,1665 cw(c6441.04,1665) 6396.8,1709.24 6424.28,1736.71 cw(c6494.99,1666) 6494.99,1766 6612.06,1766 cw(c6612,1746.69) 6625.66,1760.34 6632,1754 ccw(c6651.32,1773.32) 6651.32,1746 6663,1746 ccw(c6663,1767.73) 6678.36,1752.36 6684.93,1758.93 cw(c6702,1741.86) 6702,1766 6728,1766 cw(c6728,1746.69) 6741.66,1760.34 6748,1754 ccw(c6767.32,1773.32) 6767.32,1746 6779,1746 ccw(c6779,1767.73) 6794.36,1752.36 6800.93,1758.93 cw(c6818,1741.86) 6818,1766 6845,1766 cw(c6845,1746.69) 6858.66,1760.34 6865,1754 ccw(c6884.32,1773.32) 6884.32,1746 6896,1746 ccw(c6896,1767.73) 6911.36,1752.36 6917.93,1758.93 cw(c6935,1741.86) 6935,1766 7184.58,1766 ccw(c7184.58,1897) 7277.21,1804.37 7403.36,1930.52 cw(c7417.02,1916.86) 7417.02,1936.18 7425.99,1936.18 ccw(c7425.99,1963.51) 7445.31,1944.18 7453.56,1952.44 ccw(c7438.2,1967.8) 7459.93,1967.8 7459.93,1977.09 cw(c7484.07,1977.09) 7466.97,1994.13 ; 7467,1994.16 7679.35,2206.51 cw(c7750.06,2135.8) 7750.06,2235.8 8499.75,2235.8 cw(c8499.75,2212.26) 8511.07,2232.9 ccw(c8526.52,2248.35) 8516.22,2229.08
  Top Copper w11.5: 8516.22,2229.08 ccw(c8526.52,2248.35) 8526.52,2226.5 8668.27,2226.5 ccw(c8668.27,2306.73) v2(8725,2250)
DA3_FMC_P: C19.1 J1.A2 | length 2675.3
  Top Copper w10.5: C19.1@6347.48,1628.44 6347.48,1665 cw(c6441.04,1665) 6374.88,1731.16 6402.36,1758.63 cw(c6494.99,1666) 6494.99,1797 7184.58,1797 ccw(c7184.58,1897) 7255.29,1826.29 7657.43,2228.43 cw(c7750.06,2135.8) 7750.06,2266.8 8503.3,2266.8 ccw(c8503.3,2280.8) 8513.19,2270.89
  Top Copper w11.5: 8513.2,2270.9 cw(c8526.73,2257.35) 8526.73,2276.5 8668.27,2276.5 ccw(c8668.27,2356.73) v2(8725,2300)
DA4_ADC_N: C22.2 U1.F11
  other v11: 6441.73,1390.75
DA4_ADC_P: C21.2 U1.E11
  other v11: 6441.73,1422.24
DA4_FMC_N: C22.1 J1.Z13 | length 2446.6
  Bottom Copper w10.5: C22.1@6470.1,1394 cw(c6473.26,1384.27) 6473.26,1394.5 6586.08,1394.5 ccw(c6586.08,1458.86) 6631.59,1413.35 cw(c6657.3,1387.64) 6657.3,1424 7396.58,1424 ccw(c7396.58,1555) 7489.21,1462.37 7730.55,1703.71 cw(c7801.26,1633) 7801.26,1733 8144.58,1733 cw(c8144.58,1716.13) 8156.5,1728.06
  Bottom Copper w11.5: 8156.5,1728.06 ccw(c8170.04,1756.49) 8170.04,1725 8749.93,1725 ccw(c8749.93,1750.44) 8767.92,1732.45 ccw(c8750.83,1749.54) J1.Z13@8775,1749.54
DA4_FMC_P: C21.1 J1.Z12 | length 2444.6
  Bottom Copper w10.5: C21.1@6466.02,1426 ccw(c6467.23,1427.21) 6467.23,1425.5 6586.08,1425.5 ccw(c6586.08,1458.86) 6609.67,1435.27 cw(c6657.3,1387.64) 6657.3,1455 7396.58,1455 ccw(c7396.58,1555) 7467.29,1484.29 7717.71,1734.71 cw(c7788.42,1664) 7788.42,1764 8141,1764 ccw(c8141,1778.74) 8151.42,1768.32
  Bottom Copper w11.5: 8153.46,1770.35 cw(c8171.56,1737.44) 8171.56,1775 8730,1775 ccw(c8730,1823.28) 8764.14,1789.14 J1.Z12@8775,1800
DA5_ADC_N: C24.2 U1.D11
  other v11: 6441.73,1453.74
DA5_ADC_P: C23.2 U1.C11
  other v11: 6441.73,1485.24
DA5_FMC_N: C24.1 J1.Y11 | length 2514.2
  Bottom Copper w10.5: C24.1@6470.1,1454 cw(c6473.26,1444.27) 6473.26,1454.5 6486.22,1454.5 ccw(c6486.22,1549.07) 6553.09,1482.2 6582.55,1511.66 cw(c6631.65,1462.57) 6631.65,1532 6736,1532 cw(c6736,1516.98) 6746.62,1527.6 6752.27,1521.95 ; 6752.28,1521.94 ccw(c6764.22,1533.9) 6764.22,1517 6789.98,1517 ccw(c6789.98,1527.24) 6797.22,1520 6805.69,1528.46 cw(c6814.22,1519.93) 6814.22,1532 7310.58,1532 ccw(c7310.58,1663) 7403.21,1570.37 7636.55,1803.71 cw(c7707.26,1733) 7707.26,1833 8148.89,1833 cw(c8148.89,1817.7) 8159.71,1828.52
  Bottom Copper w11.5: 8159.71,1828.52 ccw(c8171,1852.56) 8171,1826 8780.62,1826 ccw(c8780.62,1875.19) 8815.41,1840.41 J1.Y11@8825,1850
DA5_FMC_P: C23.1 J1.Y10 | length 2512.7
  Bottom Copper w10.5: C23.1@6466.02,1486 ccw(c6467.23,1487.21) 6467.23,1485.5 6486.22,1485.5 ccw(c6486.22,1549.07) 6531.17,1504.12 6560.76,1533.71 cw(c6631.47,1463) 6631.47,1563 7310.58,1563 ccw(c7310.58,1663) 7381.29,1592.29 7623.71,1834.71 cw(c7694.42,1764) 7694.42,1864 8142.1,1864 ccw(c8142.1,1887.91) 8159,1871
  Bottom Copper w11.5: 8159,1871 cw(c8171.07,1858.94) 8171.07,1876 8780.62,1876 ccw(c8780.62,1925.19) 8815.41,1890.41 J1.Y10@8826,1901
DA6_ADC_N: C26.2 U1.B11
  other v11: 6441.73,1516.73
DA6_ADC_P: C25.2 U1.B10
  other v11: 6410.24,1516.73
DA6_FMC_N: C26.1 J1.B9 | length 2479.5
  Bottom Copper w10.5: 6440.74,1570.75 6440.74,1540.33 ccw(c6442.92,1540.33) C26.1@6441.38,1538.78 ; 6440.75,1572.33 cw(c6530.72,1570.75) 6530.72,1660.73 6572.78,1660.73 cw(c6572.78,1636.59) 6589.85,1653.66 6596.41,1647.09 ccw(c6611.78,1662.46) 6611.78,1640.73 6623.46,1640.73 ccw(c6623.46,1668.04) 6642.77,1648.72 6649.12,1655.07 cw(c6662.78,1641.42) 6662.78,1660.73 6697.78,1660.73 cw(c6697.78,1636.59) 6714.85,1653.66 6721.41,1647.09 ccw(c6736.78,1662.46) 6736.78,1640.73 6748.46,1640.73 ccw(c6748.46,1668.04) 6767.77,1648.72 ; 6767.78,1648.73 6774.12,1655.07 cw(c6787.78,1641.42) 6787.78,1660.73 6834.78,1660.73 cw(c6834.78,1645.71) 6845.4,1656.33 6851.05,1650.68 ; 6851.06,1650.67 ccw(c6863,1662.63) 6863,1645.73 6888.76,1645.73 ccw(c6888.76,1655.97) 6896,1648.73 6904.46,1657.19 cw(c6913,1648.66) 6913,1660.73 6960,1660.73 cw(c6960,1645.71) 6970.62,1656.33 6976.27,1650.68 ; 6976.28,1650.67 ccw(c6988.22,1662.63) 6988.22,1645.73 7013.98,1645.73 ccw(c7013.98,1655.97) 7021.22,1648.73 7029.69,1657.19 cw(c7038.22,1648.66) 7038.22,1660.73 7254.31,1660.73 ccw(c7254.31,1791.73) 7346.94,1699.1 7550.55,1902.71 cw(c7621.26,1832) 7621.26,1932 8148.89,1932 cw(c8148.89,1916.7) 8159.71,1927.52
  Bottom Copper w11.5: 8159.71,1927.52 ccw(c8171,1951.56) 8171,1925 8649.93,1925 ccw(c8649.93,1950.44) 8667.92,1932.45 ccw(c8650.83,1949.54) J1.B9@8675,1949.54
DA6_FMC_P: C25.1 J1.B8 | length 2481.8
  Bottom Copper w10.5: C25.1@6409.24,1538.78 6409.79,1539.34 6409.79,1574.45 cw(c6530.72,1570.75) 6530.72,1691.73 7254.31,1691.73 ccw(c7254.31,1791.73) 7325.02,1721.02 7537.71,1933.71 cw(c7608.42,1863) 7608.42,1963 8142.1,1963 ccw(c8142.1,1986.91) 8159,1970
  Bottom Copper w11.5: 8159,1970 cw(c8171.07,1957.94) 8171.07,1975 8630,1975 ccw(c8630,2023.28) 8664.14,1989.14 J1.B8@8675,2000
DA7_ADC_N: C28.2 U1.B9
  other v11: 6378.74,1516.73
DA7_ADC_P: C27.2 U1.B8
  other v11: 6347.24,1516.73
DA7_FMC_N: C28.1 J1.B5 | length 2675.7
  Bottom Copper w10.5: C28.1@6379.74,1538.78 cw(c6380.95,1539.99) 6379.24,1539.99 6379.24,1650.25 cw(c6479.24,1650.25) 6408.53,1720.96 6425.28,1737.71 cw(c6495.99,1667) 6495.99,1767 6540.78,1767 ; 6543,1767 6540.78,1767 ; 6735.77,1754.99 cw(c6716.46,1774.31) 6716.46,1747 6704.78,1747 cw(c6704.78,1768.73) 6689.41,1753.36 6682.85,1759.93 ccw(c6665.78,1742.86) 6665.78,1767 6630.78,1767 ccw(c6630.78,1747.69) 6617.12,1761.34 6610.78,1755 cw(c6591.45,1774.35) 6591.45,1747 6579.78,1747 cw(c6579.78,1768.73) 6564.41,1753.36 6557.85,1759.93 ccw(c6540.78,1742.86) 6540.78,1767 ; 6735.78,1755 6742.12,1761.34 cw(c6755.78,1747.69) 6755.78,1767 6779.56,1767 cw(c6779.56,1751.98) 6790.18,1762.6 6795.83,1756.95 ccw(c6807.78,1768.9) 6807.78,1752 ; 6808.78,1752 6834.54,1752 ; 6833.54,1752 ccw(c6833.54,1762.24) 6840.78,1755 6849.24,1763.46 cw(c6857.78,1754.93) 6857.78,1767 6904.78,1767 cw(c6904.78,1751.98) 6915.4,1762.6 6921.05,1756.95 ccw(c6933,1768.9) 6933,1752 6958.76,1752 ccw(c6958.76,1762.24) 6966,1755 6974.46,1763.46 cw(c6983,1754.93) 6983,1767 7186.58,1767 ccw(c7186.58,1898) 7279.21,1805.37 7576.55,2102.71 cw(c7647.26,2032) 7647.26,2132 8148.89,2132 cw(c8148.89,2116.7) 8159.71,2127.52
  Bottom Copper w11.5: 8159.71,2127.52 ccw(c8171,2151.56) 8171,2125 8649.93,2125 ccw(c8649.93,2150.44) 8667.92,2132.45 ccw(c8650.83,2149.54) J1.B5@8675,2149.54
DA7_FMC_P: C27.1 J1.B4 | length 2674.2
  Bottom Copper w10.5: C27.1@6347.6,1538.78 ccw(c6346.05,1540.33) 6348.24,1540.33 6348.24,1650.25 cw(c6479.24,1650.25) 6386.61,1742.88 6403.36,1759.63 cw(c6495.99,1667) 6495.99,1798 7186.58,1798 ccw(c7186.58,1898) 7257.29,1827.29 7563.71,2133.71 cw(c7634.42,2063) 7634.42,2163 8142.1,2163 ccw(c8142.1,2186.91) 8159,2170
  Bottom Copper w11.5: 8159,2170 cw(c8171.07,2157.94) 8171.07,2175 8630,2175 ccw(c8630,2223.28) 8664.14,2189.14 J1.B4@8675,2200
DB0_ADC_N: C30.2 U1.G12 | length 55.9
  Top Copper w10.5: U1.G12@6471.75,1360.25 6472,1360 6515.15,1360 C30.2@6527.5,1360.01
DB0_ADC_P: C29.2 U1.H12 | length 55.9
  Top Copper w10.5: U1.H12@6471.75,1328.75 6472,1329 C29.2@6527.5,1329
DB0_FMC_N: C30.1 J1.B12 | length 2338
  Top Copper w10.5: C30.1@6551.02,1359.02 6598.06,1359.02 cw(c6598.06,1304.06) 6636.92,1342.92 ccw(c6665.18,1371.18) 6665.18,1331.21 7456.79,1331.21 ccw(c7456.79,1431.21) 7527.5,1360.5 7954.72,1787.72 cw(c8023,1719.43) 8023,1816 8112.46,1816 ccw(c8112.46,1829.5) 8122,1819.95 cw(c8138.9,1803.05) 8138.9,1826.95 8623,1826.95 cw(c8623,1766.48) 8665.76,1809.24 v2(8675,1800) v2@8673.07,1798.07
DB0_FMC_P: C29.1 J1.B13 | length 2338.8
  Top Copper w10.5: C29.1@6551.02,1328.02 6598.06,1328.02 cw(c6598.06,1304.06) 6615,1321 ccw(c6665.18,1371.18) 6665.18,1300.21 7456.79,1300.21 ccw(c7456.79,1431.21) 7549.42,1338.58 7976.64,1765.8 cw(c8023,1719.43) 8023,1785 8112.46,1785 cw(c8112.46,1761.1) 8129.36,1778 ccw(c8138.9,1787.54) 8138.9,1774.05 8623,1774.05 cw(c8623,1706.56) 8670.72,1754.28 v2(8675,1750) v2@8669.95,1750
DB1_ADC_N: C32.2 U1.J12 | length 55.9
  Top Copper w10.5: U1.J12@6472.98,1296.51 U1.J12@6473.23,1296.26 6516.38,1296.26 C32.2@6528.73,1296.27
DB1_ADC_P: C31.2 U1.K12 | length 55.9
  Top Copper w10.5: U1.K12@6472.98,1265.01 6473.23,1265.26 C31.2@6528.73,1265.26
DB1_FMC_N: C32.1 J1.A14 | length 2385.7
  Top Copper w10.5: C32.1@6551.02,1296.02 6565.22,1296.02 cw(c6565.22,1234.22) 6608.92,1277.92 6639.55,1247.29 ccw(c6710.26,1318) 6710.26,1218 7515.58,1218 ccw(c7515.58,1318) 7586.29,1247.29 7964.41,1625.41 cw(c8057.04,1532.78) 8057.04,1663.78 8628.61,1663.78 ccw(c8628.61,1681.1) 8640.86,1668.85
  Top Copper w11.5: 8640.86,1668.85 cw(c8658.21,1651.5) 8649.54,1674.46 cw(c8658.21,1651.5) 8658.21,1676.04 8686.15,1676.04 ccw(c8686.15,1711.99) 8711.57,1686.57 v2(8725,1700)
DB1_FMC_P: C31.1 J1.A15 | length 2385.4
  Top Copper w10.5: C31.1@6551.02,1265.02 6565.22,1265.02 cw(c6565.22,1234.22) 6587,1256 6617.63,1225.37 ccw(c6710.26,1318) 6710.26,1187 7515.58,1187 ccw(c7515.58,1318) 7608.21,1225.37 7986.33,1603.49 cw(c8057.04,1532.78) 8057.04,1632.78 8633.27,1632.78 cw(c8633.27,1611.29) 8639.81,1631.76
  Top Copper w11.5: 8639.81,1631.76 cw(c8633.27,1611.29) 8648.46,1626.49 ccw(c8657.48,1651.02) 8657.48,1624.88 8690.59,1624.88 ccw(c8690.59,1647.32) 8706.45,1631.45 v2(8725,1650)
DB2_ADC_N: C34.2 U1.M11 | length 55.9
  Top Copper w10.5: C34.2@6441.74,1146.27 6441.74,1158.61 U1.M11@6441.73,1201.77 U1.M11@6441.98,1202.02
DB2_ADC_P: C33.2 U1.M10 | length 55.9
  Top Copper w10.5: U1.M10@6410.48,1202.02 6410.73,1201.77 C33.2@6410.73,1146.27
DB2_FMC_N: C34.1 J1.B16 | length 2506.5
  Top Copper w10.5: C34.1@6441.5,1123.98 6441.5,1111.29 ccw(c6460.29,1111.29) 6447,1098 ccw(c6466.66,1117.66) 6466.66,1089.86 6609,1089.86 ccw(c6609,1114) 6626.07,1096.93 6632.64,1103.49 cw(c6648,1088.13) 6648,1109.86 6659.68,1109.86 cw(c6659.68,1082.53) 6678.99,1101.87 6685.34,1095.51 ccw(c6699,1109.17) 6699,1089.86 6735,1089.86 ccw(c6735,1114) 6752.07,1096.93 6758.64,1103.49 cw(c6774,1088.13) 6774,1109.86 6785.68,1109.86 cw(c6785.68,1082.53) 6804.99,1101.87 6811.34,1095.51 ccw(c6825,1109.17) 6825,1089.86 6862,1089.86 ccw(c6862,1114) 6879.07,1096.93 6885.64,1103.49 cw(c6901,1088.13) 6901,1109.86 6912.68,1109.86 cw(c6912.68,1082.53) 6931.99,1101.87 6938.34,1095.51 ccw(c6952,1109.17) 6952,1089.86 6993,1089.86 ccw(c6993,1114) 7010.07,1096.93 7016.64,1103.49 cw(c7032,1088.13) 7032,1109.86 7043.68,1109.86 cw(c7043.68,1082.53) 7062.99,1101.87 7069.34,1095.51 ccw(c7083,1109.17) 7083,1089.86 7574.43,1089.86 ccw(c7574.43,1189.86) 7645.14,1119.14 8056.63,1530.63 cw(c8149.26,1438) 8149.26,1569 8517.81,1569 ccw(c8517.81,1594.4) 8535.77,1576.44
  Top Copper w11.5: 8535.79,1576.46 cw(c8551.95,1560.26) 8551.95,1583.14 8650.38,1583.14 ; 8650.38,1583.08 ccw(c8650.38,1601.66) 8663.5,1588.51 v2(8675,1600)
DB2_FMC_P: C33.1 J1.B17 | length 2507.2
  Top Copper w10.5: C33.1@6410.5,1123.98 6410.5,1111.64 6410.5,1111.29 ccw(c6460.29,1111.29) 6425.08,1076.08 ccw(c6466.66,1117.66) 6466.66,1058.86 7574.43,1058.86 ccw(c7574.43,1189.86) 7667.06,1097.22 8078.55,1508.71 cw(c8149.26,1438) 8149.26,1538 8526.8,1538 cw(c8526.8,1523.48) 8537.07,1533.75
  Top Copper w11.5: 8537.07,1533.75 ccw(c8559.56,1556.24) 8545.43,1527.74 ccw(c8559.56,1556.24) 8559.56,1524.43 8631.81,1524.43 ccw(c8631.81,1566.9) 8661.82,1536.84 v2(8675,1550)
DB3_ADC_N: C36.2 U1.M9 | length 55.9
  Top Copper w10.5: C36.2@6378.5,1146.02 6378.5,1158.36 6378.49,1201.52 U1.M9@6378.74,1201.77
DB3_ADC_P: C35.2 U1.M8 | length 55.9
  Top Copper w10.5: U1.M8@6347.24,1201.77 6347.49,1201.52 C35.2@6347.5,1146.02
DB3_FMC_N: C36.1 J1.A18 | length 2680
  Top Copper w10.5: C36.1@6378.5,1123.98 6378.5,1077 ccw(c6423.03,1077) 6391.55,1045.51 6417.95,1019.11 ccw(c6485.81,1086.97) 6485.81,991 6614,991 ccw(c6614,1015.14) 6631.07,998.07 6637.64,1004.64 cw(c6653,989.27) 6653,1011 6664.68,1011 cw(c6664.68,983.68) 6683.99,1003.01 6690.34,996.66 ccw(c6704,1010.31) 6704,991 6740,991 ccw(c6740,1015.14) 6757.07,998.07 6763.64,1004.64 cw(c6779,989.27) 6779,1011 6790.68,1011 cw(c6790.68,983.68) 6809.99,1003.01 6816.34,996.66 ccw(c6830,1010.31) 6830,991 6867,991 ccw(c6867,1015.14) 6884.07,998.07 6890.64,1004.64 cw(c6906,989.27) 6906,1011 6917.68,1011 cw(c6917.68,983.68) 6936.99,1003.01 6943.34,996.66 ccw(c6957,1010.31) 6957,991 6998,991 ccw(c6998,1015.14) 7015.07,998.07 7021.64,1004.64 cw(c7037,989.27) 7037,1011 7048.68,1011 cw(c7048.68,983.68) 7067.99,1003.01 7074.34,996.66 ccw(c7088,1010.31) 7088,991 7660.1,991 ccw(c7660.1,1091) 7730.81,1020.29 8137.15,1426.63 cw(c8229.78,1334) 8229.78,1465 8288.45,1465 ccw(c8288.45,1477.37) 8297.2,1468.62
  Top Copper w11.5: 8297.2,1468.62 cw(c8314.94,1450.89) 8305.29,1474.04 cw(c8314.94,1450.89) 8314.94,1475.97 8666.99,1475.97 ccw(c8666.99,1558.01) v2(8725,1500)
DB3_FMC_P: C35.1 J1.A19 | length 2684.5
  Top Copper w10.5: C35.1@6347.5,1123.98 6347.5,1111.64 6347.5,1077 ccw(c6423.03,1077) 6355.48,1043.22 ccw(c6423.03,1077) 6369.63,1023.59 6398.9,994.32 ; 6396.03,997.19 ccw(c6485.81,1086.97) 6485.81,960 7660.1,960 ccw(c7660.1,1091) 7752.73,998.37 8159.07,1404.71 cw(c8229.78,1334) 8229.78,1434 8287.7,1434 cw(c8287.7,1421.31) 8296.68,1430.28
  Top Copper w11.5: 8296.68,1430.28 ccw(c8312.47,1446.08) 8303.64,1425.56 ccw(c8312.47,1446.08) 8312.47,1423.74 8678.63,1423.74 ccw(c8678.63,1472.28) 8712.96,1437.96 v2(8725,1450)
DB4_ADC_N: C38.2 U1.G11
  other v11: 6441.73,1359.25
DB4_ADC_P: C37.2 U1.H11
  other v11: 6441.73,1327.76
DB4_FMC_N: C38.1 J1.Y14 | length 2509.3
  Bottom Copper w10.5: C38.1@6466.02,1361 ccw(c6467.23,1362.21) 6467.23,1360.5 6589.82,1360.5 cw(c6589.82,1286.82) 6641.92,1338.92 ccw(c6658.63,1355.63) 6658.63,1332 7458.58,1332 ccw(c7458.58,1432) 7529.29,1361.29 7792.63,1624.63 cw(c7885.26,1532) 7885.26,1663 8138.87,1663 ccw(c8138.87,1673.08) 8146,1665.95 8147.6,1667.55 cw(c8168,1647.14) 8168,1676
  Bottom Copper w11.5: 8168,1676 8792.56,1676 ccw(c8792.56,1713.4) 8819,1686.95 8820.02,1687.97 ccw(c8807.99,1700) J1.Y14@8825,1700
DB4_FMC_P: C37.1 J1.Y15 | length 2507.7
  Bottom Copper w10.5: C37.1@6470.1,1329 cw(c6473.26,1319.27) 6473.26,1329.5 6589.82,1329.5 cw(c6589.82,1286.82) 6620,1317 ccw(c6658.63,1355.63) 6658.63,1301 7458.58,1301 ccw(c7458.58,1432) 7551.21,1339.37 7814.55,1602.71 cw(c7885.26,1532) 7885.26,1632 8145.47,1632 cw(c8145.47,1628.42) 8148,1630.95 ccw(c8164.79,1647.74) 8164.79,1624 8168,1624
  Bottom Copper w11.5: 8168,1624 8794.39,1624 ccw(c8794.39,1654.57) 8816,1632.95 8819.31,1636.26 ccw(c8805.57,1650) J1.Y15@8825,1650 J1.Y15@8825,1647.48
DB5_ADC_N: C40.2 U1.J11
  other v11: 6441.73,1296.26
DB5_ADC_P: C39.2 U1.K11
  other v11: 6441.73,1264.76
DB5_FMC_N: C40.1 J1.Z16 | length 2477.2
  Bottom Copper w10.5: C40.1@6466.02,1296 ccw(c6467.23,1297.21) 6467.23,1295.5 6522.29,1295.5 cw(c6522.29,1199.87) 6589.91,1267.49 6610.11,1247.29 ccw(c6680.82,1318) 6680.82,1218 7516.58,1218 ccw(c7516.58,1318) 7587.29,1247.29 7865.63,1525.63 cw(c7958.26,1433) 7958.26,1564 8141,1564 ccw(c8141,1578.74) 8151.42,1568.32 8153.46,1570.35
  Bottom Copper w11.5: 8153.46,1570.35 cw(c8171.56,1537.44) 8171.56,1575 8730,1575 ccw(c8730,1623.28) 8764.14,1589.14 J1.Z16@8775,1600
DB5_FMC_P: C39.1 J1.Z17 | length 2478.1
  Bottom Copper w10.5: C39.1@6470.1,1264 cw(c6473.26,1254.27) 6473.26,1264.5 6522.29,1264.5 cw(c6522.29,1199.87) 6567.99,1245.57 6588.19,1225.37 ccw(c6680.82,1318) 6680.82,1187 7516.58,1187 ccw(c7516.58,1318) 7609.21,1225.37 7887.55,1503.71 cw(c7958.26,1433) 7958.26,1533 8144.58,1533 cw(c8144.58,1516.13) 8156.5,1528.06
  Bottom Copper w11.5: 8156.5,1528.06 ccw(c8170.04,1556.49) 8170.04,1525 8743.72,1525 8749.93,1525 ccw(c8749.93,1550.44) 8767.92,1532.45 ccw(c8750.83,1549.54) 8775,1549.54 J1.Z17@8775,1550
DB6_ADC_N: C42.2 U1.L11
  other v11: 6441.73,1233.27
DB6_ADC_P: C41.2 U1.L10
  other v11: 6410.24,1233.27
DB6_FMC_N: C42.1 J1.Y18 | length 2670.8
  Bottom Copper w10.5: C42.1@6441.14,1208.98 ccw(c6442.69,1207.43) 6441,1208.82 ccw(c6442.69,1207.43) 6440.5,1207.43 6440.5,1185.39 ccw(c6534.39,1185.39) 6468,1119 ccw(c6538.01,1189.01) 6538.01,1090 6634,1090 ; 7823.96,1296.96 7956.63,1429.63 cw(c8049.26,1337) 8049.26,1468 8146.33,1468 ccw(c8146.33,1483.98) 8157.63,1472.68 ; 7824,1297 cw(c7810.34,1310.66) 7810.34,1291.34 7801.36,1291.34 ccw(c7801.37,1264.03) 7782.06,1283.34 7773.8,1275.08 ccw(c7789.16,1259.72) 7767.43,1259.72 7767.43,1250.43 cw(c7743.29,1250.43) 7760.36,1233.36 7747,1220 cw(c7733.34,1233.66) 7733.34,1214.34 7724.37,1214.34 ccw(c7724.37,1187.03) 7705.06,1206.34 7696.8,1198.08 ccw(c7712.16,1182.72) 7690.43,1182.72 7690.43,1173.43 cw(c7666.29,1173.43) 7683.4,1156.4 ; 6634,1090 ccw(c6634,1114.14) 6634.07,1090 ; 6634,1090 6634.07,1090 ; 6634.07,1090 ccw(c6634,1114.14) 6651.07,1097.07 6657.64,1103.64 cw(c6673,1088.27) 6673,1110 6684.69,1110 cw(c6684.69,1082.69) 6703.99,1102.01 6710.34,1095.66 ccw(c6724,1109.31) 6724,1090 6759,1090 ccw(c6759,1114.14) 6776.07,1097.07 6782.64,1103.64 cw(c6798,1088.27) 6798,1110 6809.69,1110 cw(c6809.69,1082.69) 6828.99,1102.01 6835.34,1095.66 ccw(c6849,1109.31) 6849,1090 7575.58,1090 ccw(c7575.58,1190) 7646.29,1119.29 7683.36,1156.36 ; 7683.36,1156.36 ccw(c7666.29,1173.43) 7683.4,1156.4 ; 7683.36,1156.36 7683.4,1156.4
  Bottom Copper w11.5: 8157.63,1472.68 cw(c8167.9,1451.1) 8167.9,1475 8793.74,1475 ccw(c8793.74,1490.11) 8804.43,1479.43 J1.Y18@8825,1500
DB6_FMC_P: C41.1 J1.Y19 | length 2671.5
  Bottom Copper w10.5: C41.1@6409,1208.98 cw(c6407.79,1207.77) 6409.5,1207.77 6409.5,1174.16 ccw(c6507.28,1174.16) 6438.14,1105.02 6454.87,1088.29 ccw(c6525.58,1159) 6525.58,1059 7575.58,1059 ccw(c7575.58,1190) 7668.21,1097.37 7978.55,1407.71 cw(c8049.26,1337) 8049.26,1437 8142,1437 cw(c8142,1420.1) 8153.95,1432.05
  Bottom Copper w11.5: 8153.97,1432.03 ccw(c8171,1449.14) 8171,1425 8779.96,1425 ccw(c8779.96,1473.36) 8814.14,1439.15 J1.Y19@8825,1450
DB7_ADC_N: C44.2 U1.L9
  other v11: 6378.74,1233.27
DB7_ADC_P: C43.2 U1.L8
  other v11: 6347.24,1233.27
